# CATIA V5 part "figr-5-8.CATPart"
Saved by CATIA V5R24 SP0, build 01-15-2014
Part number: Part1
Bounding box of the stored display mesh (mm): x 0 to 150, y -70 to 70, z -150 to 69.804
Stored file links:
  D:\KAVITA\CATIA V5-6R2014 Project_ Kavita\CATIA V5-6R2014_partfiles\Partfiles\c05_catia_v5-6r2014_prt\figr-5-8.CATPart
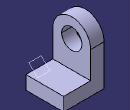
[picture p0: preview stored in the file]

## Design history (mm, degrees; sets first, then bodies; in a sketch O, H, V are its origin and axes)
Set1
  Plane1: type Angle, RefPlane face of Pad2, Direction edge of Pad2, Angle -45
Body1 (main body)
  Sketch1 on yz-plane, origin (0, 0, 0), H (0, 1, 0), V (0, 0, 1)
    arc A1 centre (0, 0) radius 70 from (70, 0) to (-70, 0) ccw
    point P1 (70, 0)
    point P2 (-70, 0)
    line L1 (-70, 0) -> (-70, -150)
    line L2 (-70, -150) -> (70, -150)
    line L3 (70, -150) -> (70, 0)
    circle A2 centre (0, 0) radius 37.5
    radius A1 = 70
    radius A2 = 37.5
    distance O L2 = 150
    coincidence: P1 H, P2 H
    tangency: L1 A1, L3 A1
    horizontal: L2 H
  Pad1: profile Sketch1, direction (1, 0, 0), length 50
  Sketch2 on face of Pad1, origin (50, 0, 0), H (0, 1, 0), V (0, 0, 1)
    line L1 (-70, -150) -> (70, -150)
    line L2 (70, -150) -> (70, -100)
    line L3 (70, -100) -> (-70, -100)
    line L4 (-70, -100) -> (-70, -150)
    reference projected line E1 (-70, -150) -> (70, -150) from edge [face of Pad1 | face of Pad1]
    reference projected line E2 (-70, 0) -> (-70, -150) from edge [face of Pad1 | face of Pad1]
    reference projected line E3 (70, -150) -> (70, 0) from edge [face of Pad1 | face of Pad1]
    length L2 = 50
    horizontal: L1 H, L3 H
    vertical: L2 V, L4 V
    coincidence: L1 E1, E2 L4, L2 E3
  Pad2: profile Sketch2, direction (1, 0, 0), length 100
